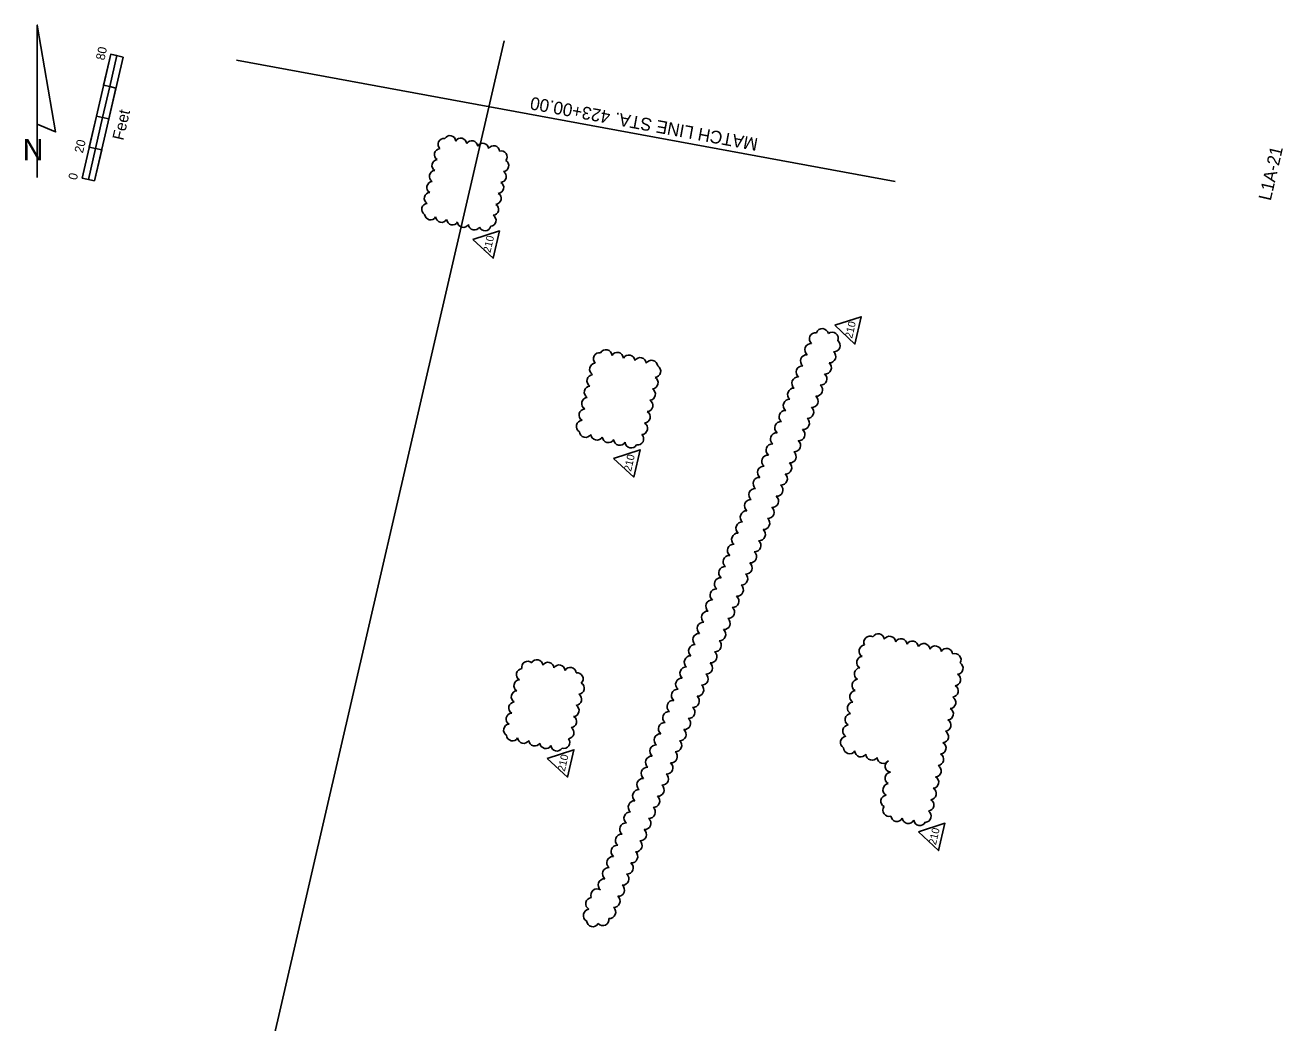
# Model space of a CAD drawing. Extents: x 930148 to 930987, y 617239 to 618551.
# Drawn here: x 930195 to 930987, y 617923 to 618551 of the extents above; entities that cross this region are included whole.
import ezdxf

# ---------------------------------------------------------------- set-up
doc = ezdxf.new("R2010")
doc.units = 0
for name, color, linetype in [('MatchLines_dp', 7, 'Continuous'), ('NorthArw_dp', 7, 'Continuous'), ('Scale_dp', 7, 'Continuous'), ('SheetLines_dp', 7, 'Continuous'), ('TextMinor', 7, 'Continuous'), ('TextShtNo', 7, 'Continuous')]:
    doc.layers.add(name, color=color, linetype=linetype)

msp = doc.modelspace()

# ---------------------------------------------------------------- linework, layer by layer
at = {"layer": 'MatchLines_dp'}
msp.add_line((930742.89, 618452.95), (930328.18, 618529.39), dxfattribs=at)
at = {"layer": 'NorthArw_dp'}
msp.add_line((930202.69, 618455.34), (930202.69, 618551.34), dxfattribs=at)
msp.add_lwpolyline([(930202.69, 618488.94), (930202.69, 618551.34), (930214.21, 618484.14)], close=True, dxfattribs=at)
at = {"layer": 'Scale_dp'}
for p, q in [((930248.91, 618533.05), (930230.95, 618455.09)), ((930256.7, 618531.25), (930248.91, 618533.05)), ((930238.75, 618453.29), (930256.7, 618531.25)), ((930230.95, 618455.09), (930238.75, 618453.29))]:
    msp.add_line(p, q, dxfattribs=at)
for points in [[(930248.32, 618512.66), (930244.42, 618513.56), (930248.91, 618533.05), (930252.81, 618532.15)], [(930247.73, 618492.27), (930243.83, 618493.17), (930248.32, 618512.66), (930252.22, 618511.76)], [(930239.34, 618473.68), (930235.44, 618474.58), (930239.93, 618494.07), (930243.83, 618493.17)], [(930238.75, 618453.29), (930234.85, 618454.19), (930239.34, 618473.68), (930243.24, 618472.78)]]:
    msp.add_lwpolyline(points, close=True, dxfattribs=at)
at = {"layer": 'TextMinor'}
msp.add_line((930247.9, 617465.07), (930496.64, 618541.42), dxfattribs=at)
at = {"layer": 'TextShtNo'}
for points in [[(930476.98, 618416.32), (930489.7, 618404.54), (930493.67, 618421.73)], [(930704.79, 618362.35), (930717.51, 618350.56), (930721.49, 618367.76)], [(930565.57, 618278.56), (930578.29, 618266.77), (930582.26, 618283.97)], [(930523.82, 618089.64), (930536.54, 618077.85), (930540.52, 618095.05)], [(930757.51, 618043.4), (930770.23, 618031.62), (930774.21, 618048.82)]]:
    msp.add_lwpolyline(points, close=True, dxfattribs=at)
for centre, radius, start, end in [((930458.72, 618476.28), 3.72, 81.49056, 226.49056), ((930462.47, 618478.07), 3.71, 4.48763, 149.48763), ((930469.37, 618476.48), 3.71, 4.48763, 149.48763), ((930476.28, 618474.88), 3.71, 4.48763, 149.48763), ((930483.18, 618473.29), 3.71, 4.48763, 149.48763), ((930456.45, 618469.88), 3.71, 94.48763, 239.48763), ((930490.08, 618471.69), 3.71, 4.48763, 149.48763), ((930494.83, 618468.42), 3.71, 321.41342, 106.41342), ((930454.86, 618462.98), 3.71, 94.48763, 239.48763), ((930495.85, 618462.9), 3.72, 274.48763, 59.48763), ((930451.67, 618449.17), 3.71, 94.48763, 239.48763), ((930453.26, 618456.08), 3.71, 94.48763, 239.48763), ((930492.66, 618449.1), 3.71, 274.48763, 59.48763), ((930494.25, 618456), 3.71, 274.48763, 59.48763), ((930450.07, 618442.27), 3.71, 94.48763, 239.48763), ((930491.06, 618442.19), 3.71, 274.48763, 59.48763), ((930448.47, 618435.37), 3.71, 94.48763, 239.48763), ((930489.47, 618435.29), 3.71, 274.48763, 59.48763), ((930450.29, 618432.46), 3.71, 184.48763, 329.48763), ((930457.19, 618430.86), 3.71, 184.48763, 329.48763), ((930464.1, 618429.27), 3.71, 184.48763, 329.48763), ((930487.87, 618428.39), 3.71, 274.48763, 59.48763), ((930471, 618427.67), 3.71, 184.48763, 329.48763), ((930477.9, 618426.08), 3.71, 184.48763, 329.48763), ((930484.56, 618425.55), 3.71, 201.49629, 346.49629), ((930692.81, 618353.78), 3.95, 82.88454, 227.88454), ((930696.98, 618356.3), 3.94, 14.19691, 159.19691), ((930703.06, 618354.03), 3.95, 339.81718, 124.81718), ((930689.91, 618346.91), 3.95, 86.38699, 231.38699), ((930704.27, 618349.61), 3.95, 265.89391, 50.89391), ((930556.72, 618341.25), 3.87, 80.36068, 225.36068), ((930560.7, 618343.1), 3.87, 4.48763, 149.48763), ((930567.9, 618341.44), 3.87, 4.48763, 149.48763), ((930575.1, 618339.77), 3.87, 4.48763, 149.48763), ((930582.3, 618338.11), 3.87, 4.48763, 149.48763), ((930687.2, 618339.89), 3.95, 86.38699, 231.38699), ((930701.5, 618342.61), 3.95, 265.89391, 50.89391), ((930554.3, 618334.64), 3.87, 94.48763, 239.48763), ((930589.49, 618336.45), 3.87, 4.48763, 149.48763), ((930591.39, 618333.41), 3.87, 274.48763, 59.48763), ((930684.49, 618332.87), 3.95, 86.38699, 231.38699), ((930698.73, 618335.61), 3.95, 265.89391, 50.89391), ((930552.64, 618327.44), 3.87, 94.48763, 239.48763), ((930589.73, 618326.21), 3.87, 274.48763, 59.48763), ((930681.78, 618325.85), 3.95, 86.38699, 231.38699), ((930695.96, 618328.61), 3.95, 265.89391, 50.89391), ((930550.97, 618320.24), 3.87, 94.48763, 239.48763), ((930588.06, 618319.02), 3.87, 274.48763, 59.48763), ((930679.07, 618318.83), 3.95, 86.38699, 231.38699), ((930690.41, 618314.62), 3.95, 265.89391, 50.89391), ((930693.18, 618321.62), 3.95, 265.89391, 50.89391), ((930547.65, 618305.84), 3.87, 94.48763, 239.48763), ((930549.31, 618313.04), 3.87, 94.48763, 239.48763), ((930586.4, 618311.82), 3.87, 274.48763, 59.48763), ((930676.36, 618311.8), 3.95, 86.38699, 231.38699), ((930687.64, 618307.62), 3.95, 265.89391, 50.89391), ((930545.98, 618298.65), 3.87, 94.48763, 239.48763), ((930584.73, 618304.62), 3.87, 274.48763, 59.48763), ((930673.65, 618304.78), 3.95, 86.38699, 231.38699), ((930684.87, 618300.62), 3.95, 265.89391, 50.89391), ((930547.88, 618295.61), 3.87, 184.48763, 329.48763), ((930583.07, 618297.42), 3.87, 274.48763, 59.48763), ((930668.23, 618290.74), 3.95, 86.38699, 231.38699), ((930670.94, 618297.76), 3.95, 86.38699, 231.38699), ((930682.1, 618293.63), 3.95, 265.89391, 50.89391), ((930555.08, 618293.95), 3.87, 184.48763, 329.48763), ((930562.27, 618292.29), 3.87, 184.48763, 329.48763), ((930569.47, 618290.62), 3.87, 184.48763, 329.48763), ((930576.67, 618288.96), 3.87, 184.48763, 329.48763), ((930580.65, 618290.81), 3.87, 260.36068, 45.36068), ((930665.51, 618283.72), 3.95, 86.38699, 231.38699), ((930679.33, 618286.63), 3.95, 265.89391, 50.89391), ((930662.8, 618276.7), 3.95, 86.38699, 231.38699), ((930676.56, 618279.63), 3.95, 265.89391, 50.89391), ((930660.09, 618269.68), 3.95, 86.38699, 231.38699), ((930673.79, 618272.63), 3.95, 265.89391, 50.89391), ((930657.38, 618262.66), 3.95, 86.38699, 231.38699), ((930671.01, 618265.64), 3.95, 265.89391, 50.89391), ((930654.67, 618255.64), 3.95, 86.38699, 231.38699), ((930665.47, 618251.64), 3.95, 265.89391, 50.89391), ((930668.24, 618258.64), 3.95, 265.89391, 50.89391), ((930651.96, 618248.62), 3.95, 86.38699, 231.38699), ((930662.7, 618244.65), 3.95, 265.89391, 50.89391), ((930646.54, 618234.57), 3.95, 86.38699, 231.38699), ((930649.25, 618241.6), 3.95, 86.38699, 231.38699), ((930659.93, 618237.65), 3.95, 265.89391, 50.89391), ((930643.83, 618227.55), 3.95, 86.38699, 231.38699), ((930657.16, 618230.65), 3.95, 265.89391, 50.89391), ((930641.12, 618220.53), 3.95, 86.38699, 231.38699), ((930654.39, 618223.65), 3.95, 265.89391, 50.89391), ((930638.4, 618213.51), 3.95, 86.38699, 231.38699), ((930651.62, 618216.66), 3.95, 265.89391, 50.89391), ((930635.69, 618206.49), 3.95, 86.38699, 231.38699), ((930648.84, 618209.66), 3.95, 265.89391, 50.89391), ((930632.98, 618199.47), 3.95, 86.38699, 231.38699), ((930646.07, 618202.66), 3.95, 265.89391, 50.89391), ((930630.27, 618192.45), 3.95, 86.38699, 231.38699), ((930640.53, 618188.67), 3.95, 265.89391, 50.89391), ((930643.3, 618195.66), 3.95, 265.89391, 50.89391), ((930627.56, 618185.43), 3.95, 86.38699, 231.38699), ((930637.76, 618181.67), 3.95, 265.89391, 50.89391), ((930622.14, 618171.39), 3.95, 86.38699, 231.38699), ((930624.85, 618178.41), 3.95, 86.38699, 231.38699), ((930634.99, 618174.67), 3.95, 265.89391, 50.89391), ((930619.43, 618164.37), 3.95, 86.38699, 231.38699), ((930632.22, 618167.67), 3.95, 265.89391, 50.89391), ((930732.15, 618164.25), 3.85, 5.43065, 150.43065), ((930616.72, 618157.34), 3.95, 86.38699, 231.38699), ((930629.44, 618160.68), 3.95, 265.89391, 50.89391), ((930723.94, 618157.22), 3.85, 95.99538, 240.99538), ((930726.97, 618162.77), 3.85, 61.58599, 206.58599), ((930739.33, 618162.72), 3.85, 5.43065, 150.43065), ((930746.5, 618161.18), 3.85, 5.43065, 150.43065), ((930753.68, 618159.65), 3.85, 5.43065, 150.43065), ((930760.85, 618158.11), 3.85, 5.43065, 150.43065), ((930768.03, 618156.58), 3.85, 5.43065, 150.43065), ((930517.22, 618147.99), 3.77, 4.48763, 149.48763), ((930614.01, 618150.32), 3.95, 86.38699, 231.38699), ((930626.67, 618153.68), 3.95, 265.89391, 50.89391), ((930722.47, 618150.03), 3.85, 95.99538, 240.99538), ((930775.21, 618155.05), 3.85, 5.43065, 150.43065), ((930780.47, 618151.84), 3.85, 326.82019, 111.82019), ((930508.14, 618142.4), 3.77, 94.48763, 239.48763), ((930511.5, 618147.06), 3.76, 48.92019, 193.92019), ((930524.22, 618146.37), 3.77, 4.48763, 149.48763), ((930531.21, 618144.75), 3.77, 4.48763, 149.48763), ((930538.21, 618143.14), 3.77, 4.48763, 149.48763), ((930542.59, 618139.72), 3.76, 314.45509, 99.45509), ((930611.29, 618143.3), 3.95, 86.38699, 231.38699), ((930623.9, 618146.68), 3.95, 265.89391, 50.89391), ((930721.01, 618142.84), 3.85, 95.99538, 240.99538), ((930781.79, 618146.39), 3.85, 275.43065, 60.43065), ((930506.52, 618135.4), 3.77, 94.48763, 239.48763), ((930543.31, 618133.79), 3.77, 274.48763, 59.48763), ((930608.58, 618136.28), 3.95, 86.38699, 231.38699), ((930618.36, 618132.69), 3.95, 265.89391, 50.89391), ((930621.13, 618139.68), 3.95, 265.89391, 50.89391), ((930719.54, 618135.65), 3.85, 95.99538, 240.99538), ((930780.25, 618139.21), 3.85, 275.43065, 60.43065), ((930504.9, 618128.41), 3.77, 94.48763, 239.48763), ((930541.69, 618126.79), 3.77, 274.48763, 59.48763), ((930605.87, 618129.26), 3.95, 86.38699, 231.38699), ((930615.59, 618125.69), 3.95, 265.89391, 50.89391), ((930718.08, 618128.46), 3.85, 95.99538, 240.99538), ((930777.18, 618124.86), 3.85, 275.43065, 60.43065), ((930778.72, 618132.04), 3.85, 275.43065, 60.43065), ((930503.29, 618121.41), 3.77, 94.48763, 239.48763), ((930540.07, 618119.79), 3.77, 274.48763, 59.48763), ((930603.16, 618122.24), 3.95, 86.38699, 231.38699), ((930612.82, 618118.69), 3.95, 265.89391, 50.89391), ((930716.62, 618121.27), 3.85, 95.99538, 240.99538), ((930775.65, 618117.68), 3.85, 275.43065, 60.43065), ((930501.67, 618114.41), 3.77, 94.48763, 239.48763), ((930538.46, 618112.79), 3.77, 274.48763, 59.48763), ((930597.74, 618108.2), 3.95, 86.38699, 231.38699), ((930600.45, 618115.22), 3.95, 86.38699, 231.38699), ((930610.05, 618111.7), 3.95, 265.89391, 50.89391), ((930715.15, 618114.07), 3.85, 95.99538, 240.99538), ((930774.11, 618110.51), 3.85, 275.43065, 60.43065), ((930500.05, 618107.41), 3.77, 94.48763, 239.48763), ((930501.89, 618104.46), 3.77, 184.48763, 329.48763), ((930536.84, 618105.79), 3.77, 274.48763, 59.48763), ((930595.03, 618101.18), 3.95, 86.38699, 231.38699), ((930607.27, 618104.7), 3.95, 265.89391, 50.89391), ((930713.69, 618106.88), 3.85, 95.99538, 240.99538), ((930772.58, 618103.33), 3.85, 275.43065, 60.43065), ((930508.89, 618102.84), 3.77, 184.48763, 329.48763), ((930515.89, 618101.23), 3.77, 184.48763, 329.48763), ((930522.89, 618099.61), 3.77, 184.48763, 329.48763), ((930529.89, 618097.99), 3.77, 184.48763, 329.48763), ((930534.19, 618099.69), 3.76, 253.62099, 38.62099), ((930592.32, 618094.16), 3.95, 86.38699, 231.38699), ((930604.5, 618097.7), 3.95, 265.89391, 50.89391), ((930712.23, 618099.69), 3.85, 95.99538, 240.99538), ((930714.21, 618096.42), 3.85, 181.35287, 326.35287), ((930771.05, 618096.16), 3.85, 275.43065, 60.43065), ((930589.61, 618087.13), 3.95, 86.38699, 231.38699), ((930601.73, 618090.7), 3.95, 265.89391, 50.89391), ((930721.26, 618094.38), 3.85, 181.35287, 326.35287), ((930728.3, 618092.34), 3.85, 181.35287, 326.35287), ((930735.35, 618090.3), 3.85, 181.35287, 326.35287), ((930740.33, 618084.75), 3.85, 117.40564, 262.40564), ((930769.51, 618088.98), 3.85, 275.43065, 60.43065), ((930586.9, 618080.11), 3.95, 86.38699, 231.38699), ((930598.96, 618083.71), 3.95, 265.89391, 50.89391), ((930740.3, 618077.12), 3.85, 97.20359, 242.20359), ((930767.98, 618081.8), 3.85, 275.43065, 60.43065), ((930584.18, 618073.09), 3.95, 86.38699, 231.38699), ((930593.42, 618069.71), 3.95, 265.89391, 50.89391), ((930596.19, 618076.71), 3.95, 265.89391, 50.89391), ((930738.99, 618069.9), 3.85, 97.20359, 242.20359), ((930766.44, 618074.63), 3.85, 275.43065, 60.43065), ((930581.47, 618066.07), 3.95, 86.38699, 231.38699), ((930590.65, 618062.71), 3.95, 265.89391, 50.89391), ((930737.68, 618062.68), 3.85, 97.20359, 242.20359), ((930764.91, 618067.45), 3.85, 275.43065, 60.43065), ((930578.76, 618059.05), 3.95, 86.38699, 231.38699), ((930587.88, 618055.72), 3.95, 265.89391, 50.89391), ((930738.95, 618056.96), 3.85, 142.93442, 287.93442), ((930761.65, 618053.21), 3.85, 272.14252, 57.14252), ((930763.37, 618060.28), 3.85, 275.43065, 60.43065), ((930573.34, 618045.01), 3.95, 86.38699, 231.38699), ((930576.05, 618052.03), 3.95, 86.38699, 231.38699), ((930585.1, 618048.72), 3.95, 265.89391, 50.89391), ((930743.95, 618053.78), 3.85, 187.20359, 332.20359), ((930751.17, 618052.47), 3.85, 187.20359, 332.20359), ((930758.39, 618051.16), 3.84, 187.20359, 332.20359), ((930570.63, 618037.99), 3.95, 86.38699, 231.38699), ((930582.33, 618041.72), 3.95, 265.89391, 50.89391), ((930567.92, 618030.97), 3.95, 86.38699, 231.38699), ((930579.56, 618034.72), 3.95, 265.89391, 50.89391), ((930565.21, 618023.95), 3.95, 86.38699, 231.38699), ((930576.79, 618027.73), 3.95, 265.89391, 50.89391), ((930562.5, 618016.93), 3.95, 86.38699, 231.38699), ((930571.25, 618013.73), 3.95, 265.89391, 50.89391), ((930574.02, 618020.73), 3.95, 265.89391, 50.89391), ((930559.79, 618009.9), 3.95, 86.38699, 231.38699), ((930568.48, 618006.74), 3.95, 265.89391, 50.89391), ((930551.94, 617998.1), 3.95, 95.97009, 240.97009), ((930555.18, 618003.51), 3.95, 57.14553, 202.14553), ((930565.7, 617999.74), 3.95, 265.89391, 50.89391), ((930550.43, 617990.72), 3.95, 95.97009, 240.97009), ((930562.93, 617992.74), 3.95, 265.89391, 50.89391), ((930552.45, 617987.58), 3.95, 184.48763, 329.48763), ((930558.74, 617988.26), 3.95, 222.90422, 7.90422)]:
    msp.add_arc(centre, radius, start, end, dxfattribs=at)

# ---------------------------------------------------------------- texts
at = {"layer": 'MatchLines_dp'}
msp.add_text('MATCH LINE STA. 423+00.00', height=8, rotation=169.55632, dxfattribs=at).set_placement((930656.91, 618479.95))
at = {"layer": 'NorthArw_dp'}
msp.add_text('N', height=13.43, dxfattribs=at).set_placement((930193.57, 618466.21))
at = {"layer": 'Scale_dp'}
for s, height, p in [('80', 5.6, (930244.87, 618528.87)), ('Feet', 7.2, (930256.85, 618478.42)), ('20', 5.6, (930231.4, 618470.42)), ('0', 5.6, (930227.51, 618453.49))]:
    msp.add_text(s, height=height, rotation=77.02872, dxfattribs=at).set_placement(p)
at = {"layer": 'SheetLines_dp'}
msp.add_text('L1A-21', height=8, rotation=76.98763, dxfattribs=at).set_placement((930979.3, 618440.37))
at = {"layer": 'TextShtNo'}
for p in [(930487.97, 618407.77), (930715.78, 618353.8), (930576.56, 618270), (930534.81, 618081.08), (930768.5, 618034.85)]:
    msp.add_text('210', height=4.799, rotation=76.98764, dxfattribs=at).set_placement(p)

doc.saveas('drawing.dxf')
